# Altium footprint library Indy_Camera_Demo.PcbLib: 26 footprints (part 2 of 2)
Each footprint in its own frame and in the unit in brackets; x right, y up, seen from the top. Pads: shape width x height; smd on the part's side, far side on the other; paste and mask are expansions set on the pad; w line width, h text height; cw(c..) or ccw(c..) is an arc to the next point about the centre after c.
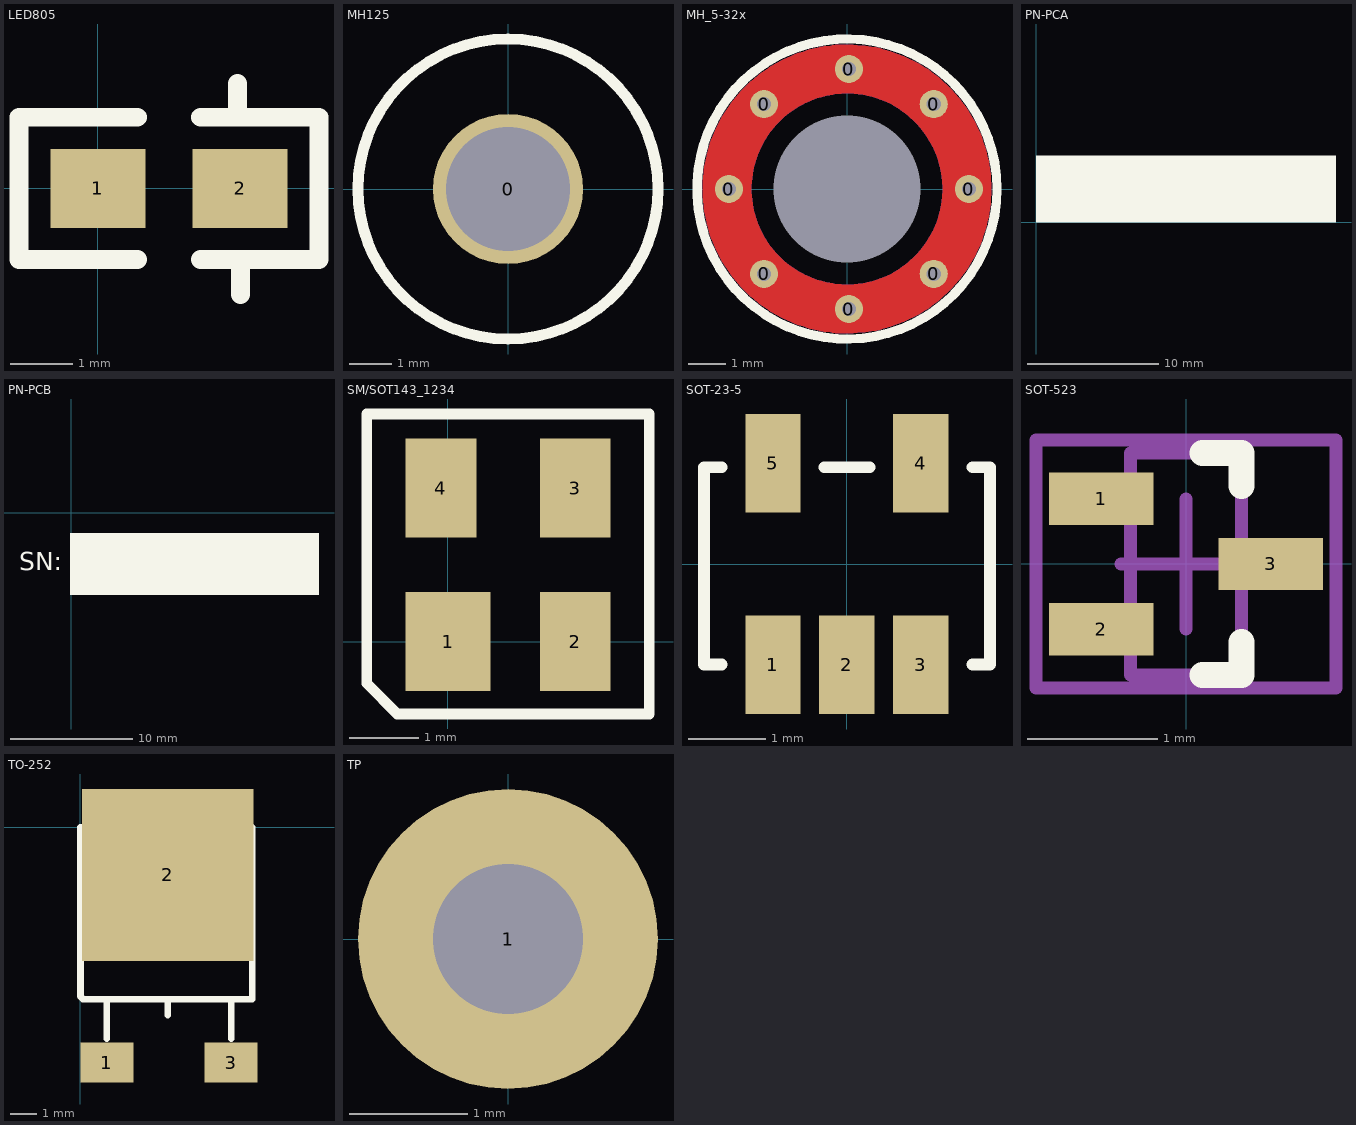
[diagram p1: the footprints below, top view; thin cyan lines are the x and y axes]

## LED805 [mil]
pads (2):
  rect 60x50 smd: 1(0,0) 2(90,0)
Top Overlay:
  lines w12: 25,-45 -50,-45 -50,45 25,45 ; 65,-45 140,-45 140,45 65,45 ; 88.5,45 88.5,66.42 ; 90.15,-67.33 90.15,-45

## MH125 [mm] "Mounting Holes Dia 0.125,Pad 0.250"
height 1.9
pads (1):
  round 3.5 hole 2.9: 0(0,0)
Top Overlay:
  circle w0.254: c0,0 r3.5

## MH_5-32x [mil] "MH for screw"
pads (9):
  round 30 hole 15: 0(-126,0) 0(-88.51,-90.51) 0(-88.51,90.51) 0(2,-128) 0(2,128) 0(92.51,-90.51) 0(92.51,90.51) 0(130,0)
  round 0 hole 156.3 unplated mask+0: 1(0,0)
Top Layer:
  circle w52.5: c0,0 r128
Bottom Layer:
  circle w52.5: c0,0 r128
Top Overlay:
  circle w10: c0,0 r160
Top Solder:
  circle w100: c0,0 r128
Bottom Solder:
  circle w100: c0,0 r128

## PN-PCA [mm] "PN-PCA silkscreen"
Top Overlay:
  rectangle: 0,0 22.86,5.08

## PN-PCB [mm] "PN-PCB cooper"
Top Overlay:
  rectangle: -0.102,-6.706 20.218,-1.626
  text "SN:" at -4.267,-5.156 h2.54

## SM/SOT143_1234 [mil]
height 433.07
pads (4):
  rect 48x56 smd: 1(0.23,0.04)
  rect 40x56 smd: 2(72.23,0.04) 3(72.23,87.04) 4(-3.77,87.04)
Top Overlay:
  lines w5.98: -45.79,129.06 -45.79,-23.62 -28.46,-40.94 -23.62,-40.94 114.21,-40.94
  lines w6: -45.77,129.04 114.23,129.04 114.23,-40.96

## SOT-23-5 [mil]
height 494.09
pads (5):
  rect 28x50 smd: 1(-37.4,-51) 2(0,-51) 3(37.4,-51) 4(37.4,51) 5(-37.4,51)
Top Overlay:
  lines w6: -63.4,-51 -72.4,-51 -72.4,49 -63.4,49 ; -11.4,49 11.6,49 ; 63.6,-51 72.6,-51 72.6,49 63.6,49

## SOT-523 [mm] "SOT-523, 3-Leads, Body 1.7x1.8mm (max), Pitch 0.50mm, IPC High Density"
height 0.9
pads (3):
  rect 0.8x0.4 smd: 1(-0.65,0.5) 2(-0.65,-0.5) 3(0.65,0)
Top Overlay:
  lines w0.2: 0.125,-0.85 0.425,-0.85 0.425,-0.6 ; 0.125,0.85 0.425,0.85 0.425,0.6
Mechanical 13:
  lines w0.1: -0.425,-0.85 0.425,-0.85 0.425,0.85 -0.425,0.85 -0.425,-0.85
Mechanical 15:
  lines w0.1: -0.5,0 0.5,0 ; 0,-0.5 0,0.5 ; -1.15,-0.95 1.15,-0.95 1.15,0.95 -1.15,0.95 -1.15,-0.95
3D body: height 0.9, standoff 0, extent -0.425,-0.85 0.425,0.85

## TO-252 [mm]
height 1.8
pads (3):
  rect 2x1.5 smd: 1(1,-8.9) 3(5.7,-8.9)
  rect 6.5x6.5 smd: 2(3.3,-1.8)
Top Overlay:
  lines w0.254: 0.9,0 0.9,0.4 1.6,1.1 4.9,1.1 5.6,0.4 5.6,0.1 ; 1,-8 1,-6.5 ; 3.3,-7.1 3.3,-6.6 ; 5.7,-8 5.7,-6.6 ; 0,-6.4 0,0 6.5,0 6.5,-6.5 0.1,-6.5 0,-6.4

## TP [mm]
height 1.8
pads (1):
  round 2.54 hole 1.27: 1(0,0)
